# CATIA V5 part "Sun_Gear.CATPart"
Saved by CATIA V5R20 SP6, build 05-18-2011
Part number: Sun_Gear
Source: Unknown
Bounding box of the stored display mesh (mm): x -7.179 to 7.179, y -7.179 to 7.179, z -2 to 2.5
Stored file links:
  E:\#01 CATIA Lecture Materials\#06 DMU\#16 DMU Page01 KIN EX16\Sun_Gear.CATPart
  C:\Program Files\Dassault Systemes\B20\win_b64\startup\materials\French\Catalog.CATMaterial
  C:\usr\gt1\projet\valve\doc\doc_2005\comp\gears\bevel_gear_files\bevel_gear.CATPart
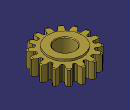
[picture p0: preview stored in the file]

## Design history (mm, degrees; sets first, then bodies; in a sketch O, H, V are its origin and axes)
Body1 (main body)
  Solid1: solid without history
